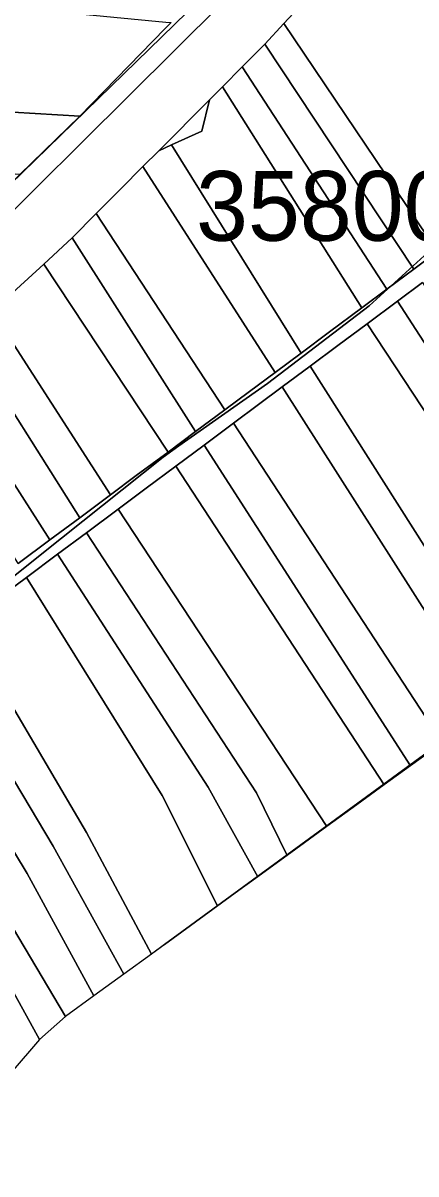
# Model space of a CAD drawing. Extents: x -535894 to -532827, y -1165802 to -1163635.
# Drawn here: x -534109.5 to -534025, y -1165431.5 to -1165184 of the extents above; entities that cross this region are included whole.
import ezdxf

# ---------------------------------------------------------------- set-up
doc = ezdxf.new("R2010")
doc.units = 0
for name, color, linetype in [('BPEJ_s', 7, 'Continuous'), ('orna_s', 7, 'Continuous'), ('ostatni_s', 7, 'Continuous'), ('trav_porost_s', 7, 'Continuous'), ('voda_s', 7, 'Continuous')]:
    doc.layers.add(name, color=color, linetype=linetype)

msp = doc.modelspace()

# ---------------------------------------------------------------- linework, layer by layer
at = {"layer": 'BPEJ_s'}
for points in [[(-534128.66, -1165234.701), (-534052.52, -1165160.48), (-533990.56, -1165093.1), (-533942.78, -1165048.02), (-533910.29, -1165011.39), (-533882.731, -1164977.94), (-533858.68, -1164945.769), (-533840.52, -1164915.19)], [(-534052.52, -1165160.48), (-534128.66, -1165234.701)], [(-533970.41, -1165171.07), (-533985.872, -1165188.218), (-533999.16, -1165206.031), (-534009.91, -1165220.44), (-534020.91, -1165231.99), (-534035.084, -1165244.865), (-534056.9, -1165261.54), (-534075.955, -1165274.993), (-534079.332, -1165277.377), (-534105.4, -1165298.17), (-534125.07, -1165313.86), (-534136.06, -1165324.773), (-534150.4, -1165346.2), (-534161.87, -1165369.29), (-534178.11, -1165393.66), (-534186.226, -1165403.375), (-534198.82, -1165412.93), (-534213.249, -1165419.389), (-534226.966, -1165422.497), (-534241.03, -1165422.65), (-534254.891, -1165420.26), (-534261.74, -1165417.867), (-534281.75, -1165380.99)], [(-534136.06, -1165324.773), (-534125.07, -1165313.86), (-534105.4, -1165298.17), (-534079.332, -1165277.377), (-534075.955, -1165274.993), (-534056.9, -1165261.54), (-534035.084, -1165244.865), (-534020.91, -1165231.99), (-534009.91, -1165220.44), (-533999.16, -1165206.031), (-533985.872, -1165188.218), (-533970.41, -1165171.07)], [(-534013.02, -1165333.89), (-534079.092, -1165382.22), (-534081.89, -1165384.25), (-534087.82, -1165388.56), (-534094.23, -1165393.22), (-534100.32, -1165397.66), (-534105.93, -1165402.64), (-534112, -1165409.73), (-534115, -1165414.12), (-534119.41, -1165420.59), (-534123.86, -1165427.13), (-534126.75, -1165433.55)]]:
    msp.add_lwpolyline(points, dxfattribs=at)
msp.add_lwpolyline([(-534075.22, -1165379.41), (-534079.092, -1165382.22), (-534013.02, -1165333.89), (-533974.66, -1165305.36), (-533943.99, -1165283.5), (-533928.089, -1165275.274), (-533945.33, -1165285.03), (-533972.2, -1165304.55), (-533978.9, -1165309.42), (-533984.1, -1165313.19), (-533990.15, -1165317.59), (-533996.63, -1165322.3), (-534003.61, -1165327.37), (-534009.54, -1165331.68), (-534014.32, -1165335.17), (-534019.31, -1165338.8), (-534026.18, -1165343.78), (-534031.82, -1165347.88), (-534037.71, -1165352.16), (-534044.14, -1165356.83), (-534052.73, -1165363.08), (-534059.04, -1165367.66), (-534067.65, -1165373.91)], close=True, dxfattribs=at)
at = {"layer": 'orna_s'}
for points in [[(-534196.09, -1165177.34), (-534144.9, -1165178.54), (-534107.5, -1165181.08), (-534103.37, -1165181.48), (-534078.8, -1165183.83), (-534077.66, -1165183.91), (-534078.91, -1165185.19), (-534097.29, -1165204.09), (-534111.65, -1165203.25), (-534176.94, -1165199.42), (-534196.74, -1165197.75)], [(-534053.42, -1165184.18), (-534020.37, -1165233.16), (-534025.49, -1165236.98), (-534057.5, -1165188.56)], [(-534057.5, -1165188.56), (-534025.49, -1165236.98), (-534031.31, -1165241.3), (-534062.36, -1165193.44)], [(-534062.36, -1165193.44), (-534031.31, -1165241.3), (-534036.68, -1165245.31), (-534066.63, -1165197.75)], [(-534066.63, -1165197.75), (-534036.68, -1165245.31), (-534043.59, -1165250.46), (-534049.71, -1165255.01), (-534077.55, -1165210.26), (-534071.03, -1165207.31), (-534069.42, -1165200.54)], [(-534071.03, -1165207.31), (-534077.55, -1165210.26), (-534080.31, -1165211.51), (-534069.42, -1165200.54)], [(-534111.65, -1165203.25), (-534097.29, -1165204.09), (-534110.19, -1165216.6), (-534122.97, -1165215.71)], [(-534080.31, -1165211.51), (-534077.55, -1165210.26), (-534049.71, -1165255.01), (-534055.31, -1165259.18), (-534083.69, -1165214.91)], [(-534083.69, -1165214.91), (-534055.31, -1165259.18), (-534060.78, -1165263.26), (-534066.12, -1165267.23), (-534093.73, -1165225.02), (-534088.44, -1165219.7)], [(-534093.73, -1165225.02), (-534066.12, -1165267.23), (-534072.4, -1165271.89), (-534098.91, -1165230.23)], [(-534098.91, -1165230.23), (-534072.4, -1165271.89), (-534078.3, -1165276.29), (-534105.03, -1165235.88)], [(-534105.03, -1165235.88), (-534078.3, -1165276.29), (-534085.13, -1165281.37), (-534090.65, -1165285.49), (-534116.12, -1165246.09), (-534110.88, -1165241.27)], [(-534116.12, -1165246.09), (-534090.65, -1165285.49), (-534097.28, -1165290.43), (-534121.92, -1165251.44)], [(-534121.92, -1165251.44), (-534097.28, -1165290.43), (-534103.68, -1165295.19), (-534128.1, -1165257.13)], [(-534128.1, -1165257.13), (-534103.68, -1165295.19), (-534110.5, -1165300.26), (-534133.62, -1165262.47), (-534128.78, -1165257.75)]]:
    msp.add_lwpolyline(points, close=True, dxfattribs=at)
at = {"layer": 'ostatni_s'}
for points in [[(-534066.72, -1165179.82), (-534136.8, -1165249.37), (-534194.29, -1165306.12), (-534200.89, -1165312.54), (-534205.31, -1165316.61), (-534215.14, -1165313.24), (-534244.31, -1165303.28), (-534241.33, -1165297.17), (-534240.88, -1165296.25), (-534228.15, -1165300.5), (-534203.98, -1165308.56), (-534201.96, -1165306.58), (-534145.83, -1165251.25), (-534131.84, -1165237.61), (-534110.19, -1165216.6), (-534097.29, -1165204.09), (-534078.91, -1165185.19), (-534077.66, -1165183.91)], [(-534110.5, -1165300.26), (-534103.68, -1165295.19), (-534097.28, -1165290.43), (-534090.65, -1165285.49), (-534085.13, -1165281.37), (-534078.3, -1165276.29), (-534072.4, -1165271.89), (-534066.12, -1165267.23), (-534060.78, -1165263.26), (-534055.31, -1165259.18), (-534049.71, -1165255.01), (-534043.59, -1165250.46), (-534036.68, -1165245.31), (-534031.31, -1165241.3), (-534025.49, -1165236.98), (-534020.37, -1165233.16)], [(-534023.58, -1165239.87), (-534028.98, -1165243.88), (-534035.47, -1165248.71), (-534041.8, -1165253.42), (-534047.73, -1165257.84), (-534053.75, -1165262.31), (-534058.84, -1165266.1), (-534064.21, -1165270.09), (-534070.53, -1165274.8), (-534076.64, -1165279.34), (-534083, -1165284.08), (-534089.06, -1165288.58), (-534095.86, -1165293.64), (-534102.06, -1165298.25), (-534108.76, -1165303.24), (-534115.44, -1165308.22)]]:
    msp.add_lwpolyline(points, dxfattribs=at)
at = {"layer": 'trav_porost_s'}
for points in [[(-534024.54, -1165159.35), (-534019.14, -1165162.52), (-534014.17, -1165173.12), (-534012.92, -1165190.05), (-534005.15, -1165199.61), (-533989.71, -1165212.03), (-533992.77, -1165214.76), (-533945.33, -1165285.03), (-533972.2, -1165304.55), (-534018.44, -1165236.03), (-534020.37, -1165233.16), (-534053.42, -1165184.18), (-534033.26, -1165162.58), (-534030.52, -1165163.57)], [(-534023.58, -1165239.87), (-533978.9, -1165309.42), (-533984.1, -1165313.19), (-534028.98, -1165243.88)], [(-534028.98, -1165243.88), (-533984.1, -1165313.19), (-533990.15, -1165317.59), (-534035.47, -1165248.71)], [(-534035.47, -1165248.71), (-533990.15, -1165317.59), (-533996.63, -1165322.3), (-534003.61, -1165327.37), (-534047.73, -1165257.84), (-534041.8, -1165253.42)], [(-534047.73, -1165257.84), (-534003.61, -1165327.37), (-534009.54, -1165331.68), (-534053.75, -1165262.31)], [(-534053.75, -1165262.31), (-534009.54, -1165331.68), (-534014.32, -1165335.17), (-534019.31, -1165338.8), (-534064.21, -1165270.09), (-534058.84, -1165266.1)], [(-534064.21, -1165270.09), (-534019.31, -1165338.8), (-534026.18, -1165343.78), (-534070.53, -1165274.8)], [(-534070.53, -1165274.8), (-534026.18, -1165343.78), (-534031.82, -1165347.88), (-534076.64, -1165279.34)], [(-534076.64, -1165279.34), (-534031.82, -1165347.88), (-534037.71, -1165352.16), (-534044.14, -1165356.83), (-534089.06, -1165288.58), (-534083, -1165284.08)], [(-534089.06, -1165288.58), (-534044.14, -1165356.83), (-534052.73, -1165363.08), (-534059.26, -1165349.61), (-534095.86, -1165293.64)], [(-534095.86, -1165293.64), (-534059.26, -1165349.61), (-534052.73, -1165363.08), (-534059.04, -1165367.66), (-534069.65, -1165348.37), (-534102.06, -1165298.25)], [(-534102.06, -1165298.25), (-534069.65, -1165348.37), (-534059.04, -1165367.66), (-534067.65, -1165373.91), (-534079.55, -1165350.17), (-534108.76, -1165303.24)], [(-534108.76, -1165303.24), (-534079.55, -1165350.17), (-534067.65, -1165373.91), (-534075.22, -1165379.41), (-534081.89, -1165384.25), (-534095.85, -1165358.13), (-534121.89, -1165313.8), (-534115.44, -1165308.22)], [(-534128.01, -1165319.11), (-534121.89, -1165313.8), (-534095.85, -1165358.13), (-534081.89, -1165384.25), (-534087.82, -1165388.56), (-534103.02, -1165361.05)], [(-534134.26, -1165324.52), (-534128.01, -1165319.11), (-534103.02, -1165361.05), (-534087.82, -1165388.56), (-534094.23, -1165393.22), (-534108.57, -1165366.89)], [(-534140.55, -1165329.98), (-534134.26, -1165324.52), (-534108.57, -1165366.89), (-534094.23, -1165393.22), (-534100.32, -1165397.66)], [(-534146.4, -1165335.06), (-534140.55, -1165329.98), (-534100.32, -1165397.66), (-534105.93, -1165402.64), (-534123.09, -1165371.57)], [(-534151.85, -1165340.25), (-534146.4, -1165335.06), (-534123.09, -1165371.57), (-534105.93, -1165402.64), (-534112, -1165409.73)]]:
    msp.add_lwpolyline(points, close=True, dxfattribs=at)
at = {"layer": 'voda_s'}
for points in [[(-534033.26, -1165162.58), (-534053.42, -1165184.18), (-534057.5, -1165188.56), (-534062.36, -1165193.44), (-534066.63, -1165197.75), (-534069.42, -1165200.54), (-534080.31, -1165211.51), (-534083.69, -1165214.91), (-534088.44, -1165219.7), (-534093.73, -1165225.02), (-534098.91, -1165230.23), (-534105.03, -1165235.88), (-534110.88, -1165241.27)], [(-534136.8, -1165249.37), (-534066.72, -1165179.82)]]:
    msp.add_lwpolyline(points, dxfattribs=at)

# ---------------------------------------------------------------- texts
at = {"layer": 'BPEJ_s'}
msp.add_text('35800/II.', height=15, dxfattribs=at).set_placement((-534072.282, -1165230.865))

doc.saveas('drawing.dxf')
